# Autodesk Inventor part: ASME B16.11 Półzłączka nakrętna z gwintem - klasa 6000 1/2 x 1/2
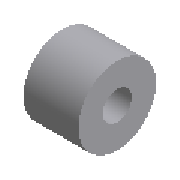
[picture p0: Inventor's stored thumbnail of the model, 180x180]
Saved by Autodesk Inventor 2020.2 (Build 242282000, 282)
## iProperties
Manager: www.cadconsulting.pl
Company: Fabian Stasiak CAD Consulting
NAME: PIPING: ASME B16.11 Half Coupling Threaded - Class 6000
DATA: <meta><inlinegroups number="1" deflen="6.0325"></inlinegroups><connections number="2"></connections><angles><a>3.14159265358979</a></angles></meta>
IsCustomPart: 0
Created: 2014-02
Part Number: ASME B16.11 Półzłączka nakrętna z gwintem - klasa 6000 1/2 x 1/2
Material: Stal
Description: Złączka połówkowa, gwintowana - klasa 6000
Document SubType Name: Modeling
Standard: ASME B16.11
Designer: F.Stasiak
Standard Revision: 2005
Standards Organization: ANSI
Language: pl-PL
Size Designation: 1/2 x 1/2
Categories: <MemberInstance><Categories><Category DisplayName="Rury cienko- i grubościenne" InternalName="4347fa0f-2144-441d-94cd-e3e15c92b736" Mnemonic="TUBEANDPIPE"><Cate
Density: 1 g/cm^3
Appearance: Płyta
Catalog Web Link: www.expertbooks.pl
Author: F.Stasiak
Subject: Zbiór ćwiczeń. Autodesk Inventor 2020. Kurs Professional
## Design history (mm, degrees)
sketch "Sketch1"
  geometry: L1 (0, 0)-(23.876, 0); L2 (23.876, 0)-(23.876, 8.737); L3 (23.876, 8.737)-(13.556, 8.737); L4 (13.556, 8.737)-(0, 9.16); L5 (0, 9.16)-(0, 0); L6 (23.876, 19.05)-(0, 19.05); L7 (0, 19.05)-(0, 9.16); L8 (23.876, 19.05)-(23.876, 8.737); L9 (13.556, 8.737)-(13.556, 0)
  constraints: 18 end point, 3 parallel, 3 perpendicular, 1 horizontal, 1 point on line, 1 vertical
  dimensions: "d0" = 18.32077 diameter of L4.end L1 (= MD); "d1" = 38.1 diameter of L6.end L1 (= D); "d2" = 23.876 distance of L6.start L6.end (= 0.5 x W1); "d3" = 1.78991 deg angle of L1 L4; "d4" = 13.55598 horizontal distance of L3.end L4.end (= L)
revolve "Revolve1" stored, may be unused: angle "d6" = 90 deg
workpoint "Work Point2"
workaxis "Work Axis2"
workpoint "Work Point3"
workaxis "Work Axis3"
workpoint "Work Point4"
body "Solid1"
feature "Gwint1" dims "d16" = 25.4, "d17" = 0
other parameters: "W1" = 47.752 [user parameter; used in 1 equation term], "D" = 38.1 [user parameter; used in 1 equation term], "L" = 13.55598 [user parameter; used in 1 equation term], "MD" = 18.32077 [user parameter; used in 1 equation term], "Size_Designation" = 12.345 [user parameter]
